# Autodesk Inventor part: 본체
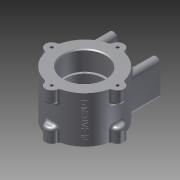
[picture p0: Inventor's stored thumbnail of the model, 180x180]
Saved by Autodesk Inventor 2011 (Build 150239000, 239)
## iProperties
Created: 2015-03
Part Number: 본체
Document SubType Name: Modeling
Designer: LINEART07
Density: 1 g/cm^3
Author: LINEART07
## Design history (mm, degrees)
sketch "스케치5"
  geometry: C1 r 37 at (0, 0); 1 further point
  constraints: 1 centre point, 1 coincident
  dimensions: "d17" = 74 diameter of C1
extrude "돌출4" new body sketch "스케치5" distance "d18" = 52; taper "d19" = 0 deg
sketch "스케치6"
  geometry: A1 r 37 centre (0, 0) between (-6.969, 36.338) and (6.969, 36.338) reference; A2 r 7 centre (0, 37) between (6.969, 36.338) and (-6.969, 36.338)
  constraints: 4 point on circle, 1 centre point
  dimensions: "d20" = 7 radius of A2
extrude "돌출5" join sketch "스케치6" distance "d21" = 15; taper "d22" = 0 deg
sketch "스케치7"
  geometry: A1 r 7 centre (0, 37) between (6.969, 36.338) and (-6.969, 36.338) reference; A2 r 37 centre (0, 0) between (6.969, 36.338) and (-6.969, 36.338) reference; A3 r 7 centre (0, 37) between (6.969, 36.338) and (-6.969, 36.338)
  constraints: 4 point on circle, 1 centre point, 1 coincident
extrude "돌출6" join sketch "스케치7" distance "d26" = 15; taper "d27" = 0 deg
node "작업 평면2"
sketch "스케치8"
  geometry: L1 (-36.338, 52)-(-6.969, 52) reference; L2 (7, 52)-(-7, 52) reference; L3 (-7, 0)-(7, 0) reference; L4 (0, 0)-(0, 52); L5 (-24, 58.838)-(-24, -13.337); L6 (-55.49, 41)-(59.857, 41); L7 (-59.657, 11)-(61.023, 11); L8 (0, 26)-(-59.491, 26) reference; L9 (-29, 41)-(-29, 11); L10 (-19, 11)-(-19, 41); A1 r 5 centre (-24, 41) between (-19, 41) and (-29, 41); A2 r 5 centre (-24, 11) between (-29, 11) and (-19, 11); 3 further points
  constraints: 14 end point, 8 point on line, 4 point on circle, 3 parallel, 2 centre point, 2 midpoint, 2 perpendicular, 1 horizontal
  dimensions: "d32" = 24 distance between parallel lines of L4 L5; "d33" = 15 distance between parallel lines of L7 L8; "d34" = 15 distance between parallel lines of L6 L8
extrude "돌출7" join sketch "스케치8" stored distance "d35" = 15; taper "d36" = 0 deg
sketch "스케치9"
  geometry: L1 (-6.969, 15)-(6.969, 15) reference; L2 (6.969, 0)-(6.969, 15) reference; L3 (-6.969, 0)-(6.969, 0) reference; L4 (-6.969, 15)-(-6.969, 0) reference; L5 (31.749, 11)-(31.749, 41) reference; L6 (22.978, 41)-(22.978, 11) reference; L7 (31.749, 41)-(31.749, 11) reference; L8 (22.978, 11)-(22.978, 41) reference; L9 (6.969, 52)-(6.969, 37) reference; L10 (6.969, 37)-(-6.969, 37) reference; L11 (-6.969, 37)-(-6.969, 52) reference; L12 (-6.969, 52)-(-36.338, 52) reference; L13 (-36.338, 52)-(-36.338, 37) reference; L14 (-36.338, 37)-(-36.338, 37) reference; L15 (-36.338, 37)-(-36.338, 52) reference; L16 (-36.338, 52)-(-6.969, 52) reference; L17 (-6.969, 52)-(-6.969, 37) reference; L18 (-6.969, 37)-(6.969, 37) reference; L19 (6.969, 37)-(6.969, 52) reference; L20 (6.969, 52)-(36.338, 52) reference; L21 (36.338, 52)-(36.338, 37) reference; L22 (36.338, 37)-(36.338, 37) reference; L23 (36.338, 37)-(36.338, 52) reference; L24 (36.338, 52)-(6.969, 52) reference; L25 (-6.969, 0)-(-6.969, 15) reference; L26 (-6.969, 15)-(6.969, 15) reference; L27 (6.969, 15)-(6.969, 0) reference; L28 (36.338, 0)-(6.969, 0) reference; L29 (36.338, 0)-(36.338, 15) reference; L30 (36.338, 15)-(36.338, 15) reference; L31 (36.338, 15)-(36.338, 0) reference; L32 (6.969, 0)-(36.338, 0) reference; L33 (6.969, 0)-(6.969, 15) reference; L34 (6.969, 15)-(-6.969, 15) reference; L35 (-6.969, 15)-(-6.969, 0) reference; L36 (-36.338, 0)-(-6.969, 0) reference; L37 (-36.338, 0)-(-36.338, 15) reference; L38 (-36.338, 15)-(-36.338, 15) reference; L39 (-36.338, 15)-(-36.338, 0) reference; L40 (-6.969, 0)-(-36.338, 0) reference; L41 (6.969, 37)-(-6.969, 37) reference; L42 (-6.969, 52)-(-6.969, 37) reference; L43 (6.969, 52)-(-6.969, 52) reference; L44 (6.969, 37)-(6.969, 52) reference; L45 (0, -9.9)-(0, 64.335) reference; L46 (0, 0)-(-23.5, 0); L47 (-23.5, 0)-(-23.5, 22); L48 (-23.5, 22)-(0, 22); L49 (0, 22)-(0, 0); L50 (0, 52)-(-23.5, 52); L51 (-23.5, 52)-(-23.5, 30); L52 (-23.5, 30)-(0, 30); L53 (0, 30)-(0, 52); L54 (0, 22)-(-21, 22); L55 (-21, 22)-(-21, 30); L56 (-21, 30)-(0, 30); L57 (0, 30)-(0, 22)
  constraints: 26 end point, 7 parallel, 4 horizontal alignment, 3 horizontal, 3 perpendicular, 2 point on line, 1 midpoint, 1 vertical
  dimensions: "d82" = 23.5 distance between parallel lines of L45 L47; "d83" = 23.5 distance between parallel lines of L53 L51; "d84" = 22 distance between parallel lines of L54 L46; "d85" = 22 distance between parallel lines of L50 L56
revolve "회전1" sketch "스케치9" stored, may be unused: angle "d37" = 90 deg
sketch "스케치10"
  geometry: A1 r 7 centre (-37, 0) between (-36.338, 6.969) and (-36.338, -6.969) reference; 1 further point
  constraints: 1 coincident
hole "Hole1" sketch "스케치10" at (-37, 0) diameter "d38" = 3.242; stored, may be unused: countersink angle "d42" = 90 deg, drill point angle "d44" = 118 deg; dims "d39" = 8, "d40" = 4, "d41" = 2, "d43" = 11
sketch "스케치11"
  geometry: A1 r 7 centre (0, -37) between (-6.969, -36.338) and (6.969, -36.338) reference; 1 further point
  constraints: 1 coincident
hole "Hole2" sketch "스케치11" at (0, -37) diameter "d48" = 3.242; stored, may be unused: countersink angle "d52" = 90 deg, drill point angle "d54" = 118 deg; dims "d49" = 8, "d50" = 4, "d51" = 2, "d53" = 11
sketch "스케치12"
  geometry: A1 r 5 centre (24, -11) between (29, -11) and (19, -11) reference; A2 r 5 centre (24, -41) between (19, -41) and (29, -41) reference; 3 further points
  constraints: 2 coincident
hole "Hole4" sketch "스케치12" at (24, -11), (24, -41) diameter "d65" = 4.134; stored, may be unused: countersink angle "d69" = 90 deg, drill point angle "d71" = 118 deg; dims "d66" = 6, "d67" = 4, "d68" = 2, "d70" = 8
fillet "모깎기1" dims "d72" = 0.3
fillet "모깎기2" dims "d73" = 3
fillet "모깎기3" dims "d74" = 3
chamfer "모따기1" distance "d75" = 1; stored, may be unused: second distance "d76" = 2, angle "d77" = 45 deg
node "작업 평면6"
  node "작업 평면5"
sketch "스케치15"
  geometry: L1 (36.628, 41)-(36.628, 11) reference; L2 (18.921, 52)-(-18.921, 52) reference; L3 (31.796, 40)-(31.796, 52) reference; L4 (24.303, 34)-(27.899, 34) reference; L5 (18.921, 52)-(18.921, 40) reference; L6 (-18.921, 40)-(-18.921, 52) reference; L7 (-27.899, 34)-(-24.303, 34) reference; L8 (-31.796, 52)-(-31.796, 40) reference; L9 (-31.796, 52)-(-31.796, 52) reference; L10 (-31.796, 40)-(-31.796, 52) reference; L11 (-24.303, 34)-(-27.899, 34) reference; L12 (-18.921, 52)-(-18.921, 40) reference; L13 (-5.233, 11)-(-5.233, 41) reference; L14 (18.921, 0)-(-18.921, 0) reference; L15 (-18.921, 12)-(-18.921, 0) reference; L16 (-27.899, 18)-(-24.303, 18) reference; L17 (-31.796, 0)-(-31.796, 12) reference; L18 (-31.796, 0)-(-31.796, 0) reference; L19 (-31.796, 12)-(-31.796, 0) reference; L20 (-24.303, 18)-(-27.899, 18) reference; L21 (-18.921, 0)-(-18.921, 12) reference; L22 (18.921, 12)-(18.921, 0) reference; L23 (27.899, 18)-(24.303, 18) reference; L24 (31.796, 0)-(31.796, 12) reference; L25 (-37, 0)-(-37, 52) reference; L26 (0, 0)-(0, 52); L27 (13.514, 41)-(13.514, 11) reference; L28 (31.796, 52)-(31.796, 40) reference; L29 (31.796, 52)-(31.796, 52) reference; L30 (-18.921, 52)-(18.921, 52) reference; L31 (18.921, 40)-(18.921, 52) reference; L32 (27.899, 34)-(24.303, 34) reference; L33 (18.921, 0)-(18.921, 12) reference; L34 (-18.921, 0)-(18.921, 0) reference; L35 (31.796, 0)-(31.796, 0) reference; L36 (31.796, 12)-(31.796, 0) reference; L37 (24.303, 18)-(27.899, 18) reference; L38 (34.444, 11)-(34.444, 41) reference; 4 further points
  constraints: 5 horizontal alignment, 2 end point, 2 midpoint, 1 coincident, 1 parallel, 1 vertical alignment, 17 other
  node "투영된 루프5"
sketch "스케치16"
  geometry: 1 further point
feature "엠보싱1" dims "d26" = 15, "d80" = 0.5, "d81" = 0
node "솔리드2"
pattern_circular "원형 패턴2" dims angle "d24" = 360 deg
pattern_circular "원형 패턴3" dims angle "d29" = 360 deg
mirror "대칭1"
pattern_circular "원형 패턴4" dims angle "d46" = 360 deg
pattern_circular "원형 패턴5" dims angle "d56" = 360 deg
mirror "대칭2"
node "투영된 루프1"
node "투영된 루프2"
node "투영된 루프3"
node "투영된 루프4"
node "작업축1"
other parameters: "d31" = 56, "d78" = 45 deg
